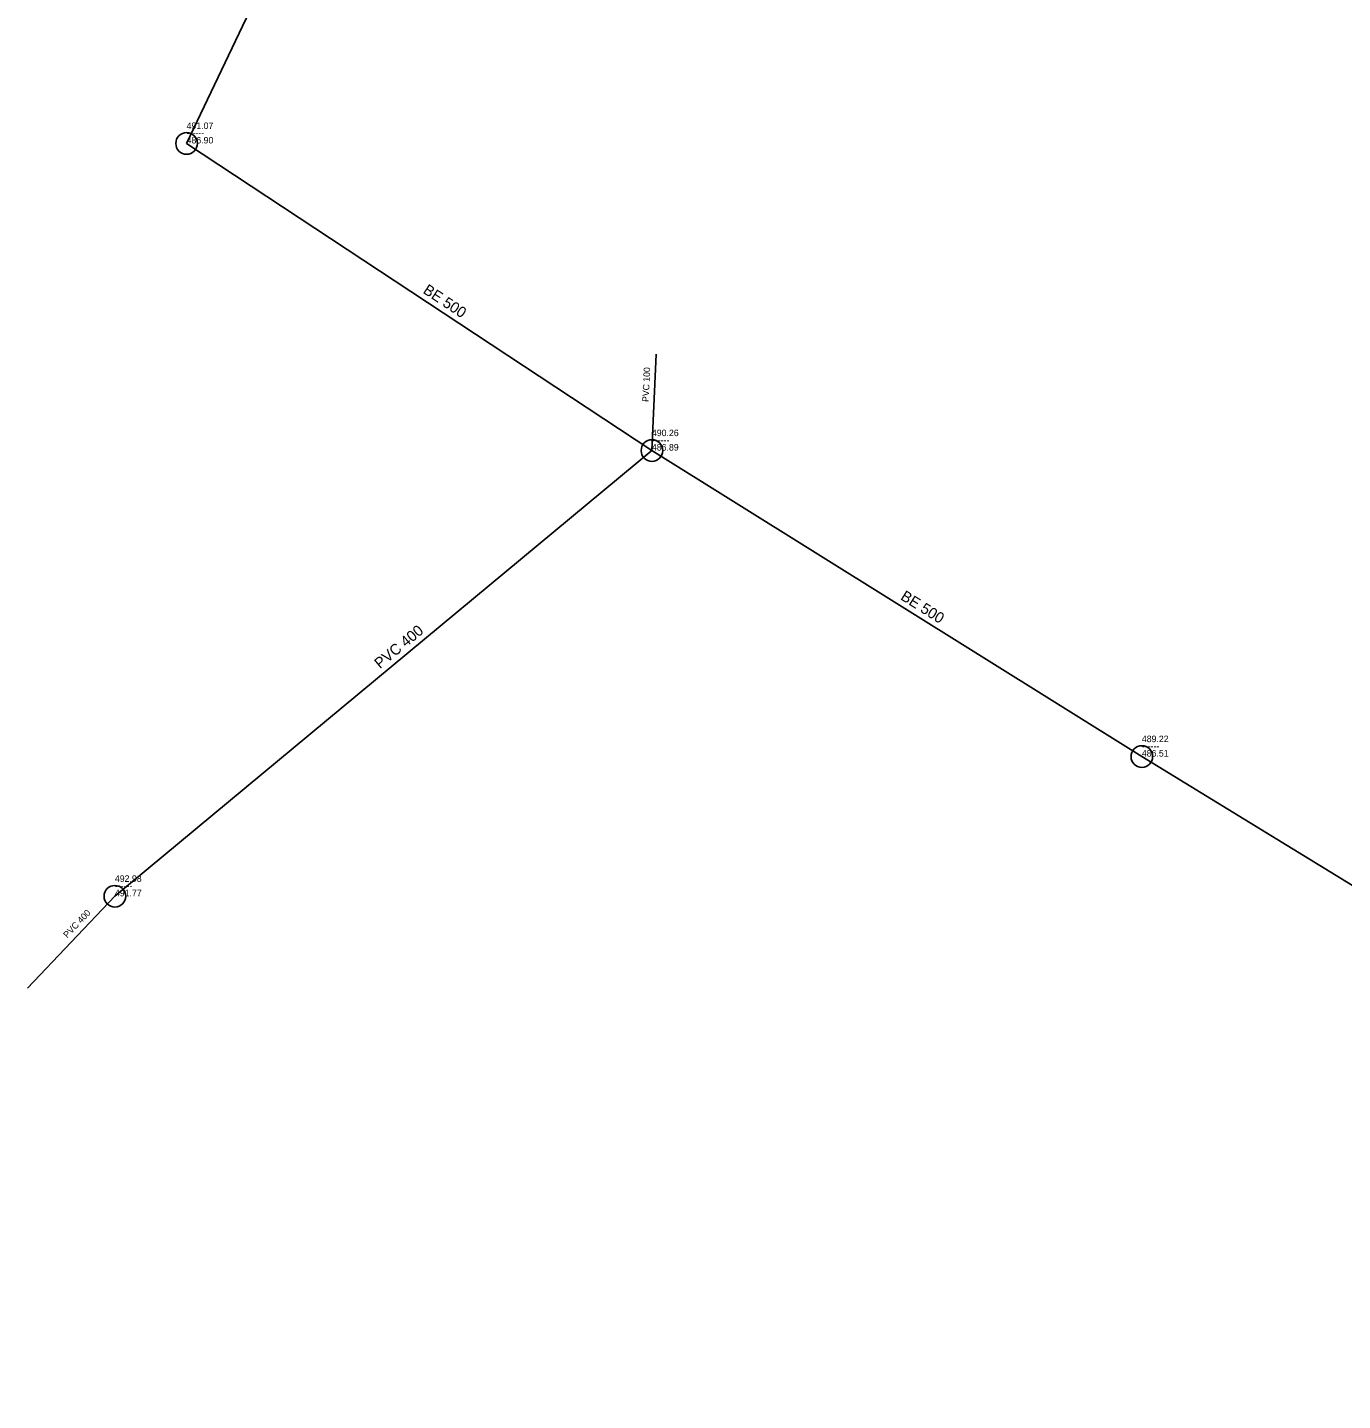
# Model space of a CAD drawing. Extents: x -770228 to -769930, y -1182222 to -1181927.
# Drawn here: x -770215.8 to -770154.9, y -1182131.9 to -1182068.3 of the extents above; entities that cross this region are included whole.
import ezdxf

# ---------------------------------------------------------------- set-up
doc = ezdxf.new("R2010")
doc.units = 0
for name, color, linetype in [('Kanalizační přípojky', 7, 'Continuous'), ('Kanalizační stoka', 7, 'Continuous'), ('Kanalizační šachty', 7, 'Continuous'), ('Popis', 7, 'Continuous')]:
    doc.layers.add(name, color=color, linetype=linetype)

msp = doc.modelspace()

# ---------------------------------------------------------------- linework, layer by layer
at = {"layer": 'Kanalizační přípojky'}
for points in [[(-770186.71, -1182083.46), (-770186.91, -1182087.93)], [(-770215.83, -1182112.82), (-770211.78, -1182108.57)]]:
    msp.add_lwpolyline(points, dxfattribs=at)
at = {"layer": 'Kanalizační stoka'}
for points in [[(-770195.33, -1182046.18), (-770208.46, -1182073.71)], [(-770208.46, -1182073.71), (-770186.91, -1182087.93)], [(-770211.78, -1182108.57), (-770186.91, -1182087.93)], [(-770186.91, -1182087.93), (-770164.22, -1182102.1)], [(-770164.22, -1182102.1), (-770115.52, -1182131.92)]]:
    msp.add_lwpolyline(points, dxfattribs=at)
at = {"layer": 'Kanalizační šachty'}
for centre in [(-770208.46, -1182073.71), (-770186.91, -1182087.93), (-770164.22, -1182102.1), (-770211.78, -1182108.57)]:
    msp.add_circle(centre, 0.5, dxfattribs=at)

# ---------------------------------------------------------------- texts
at = {"layer": 'Popis'}
for s, height, rotation, p in [('491.07', 0.303, 0, (-770208.46, -1182073.043)), ('------', 0.303, 0, (-770208.46, -1182073.377)), ('486.90', 0.303, 0, (-770208.46, -1182073.71)), ('BE 500', 0.5, 326.58074, (-770197.547, -1182080.611)), ('PVC 100', 0.3, 87.43814, (-770187.06, -1182085.684)), ('490.26', 0.303, 360, (-770186.91, -1182087.263)), ('486.89', 0.303, 360, (-770186.91, -1182087.93)), ('------', 0.303, 360, (-770186.91, -1182087.597)), ('BE 500', 0.5, 328.01505, (-770175.433, -1182094.803)), ('PVC 400', 0.5, 39.68981, (-770199.505, -1182098.058)), ('489.22', 0.303, 0, (-770164.22, -1182101.433)), ('486.51', 0.303, 0, (-770164.22, -1182102.1)), ('------', 0.303, 0, (-770164.22, -1182101.767)), ('492.98', 0.303, 0, (-770211.78, -1182107.903)), ('491.77', 0.303, 0, (-770211.78, -1182108.57)), ('------', 0.303, 0, (-770211.78, -1182108.237)), ('PVC 400', 0.3, 46.38035, (-770213.986, -1182110.523))]:
    msp.add_text(s, height=height, rotation=rotation, dxfattribs=at).set_placement(p)

doc.saveas('drawing.dxf')
